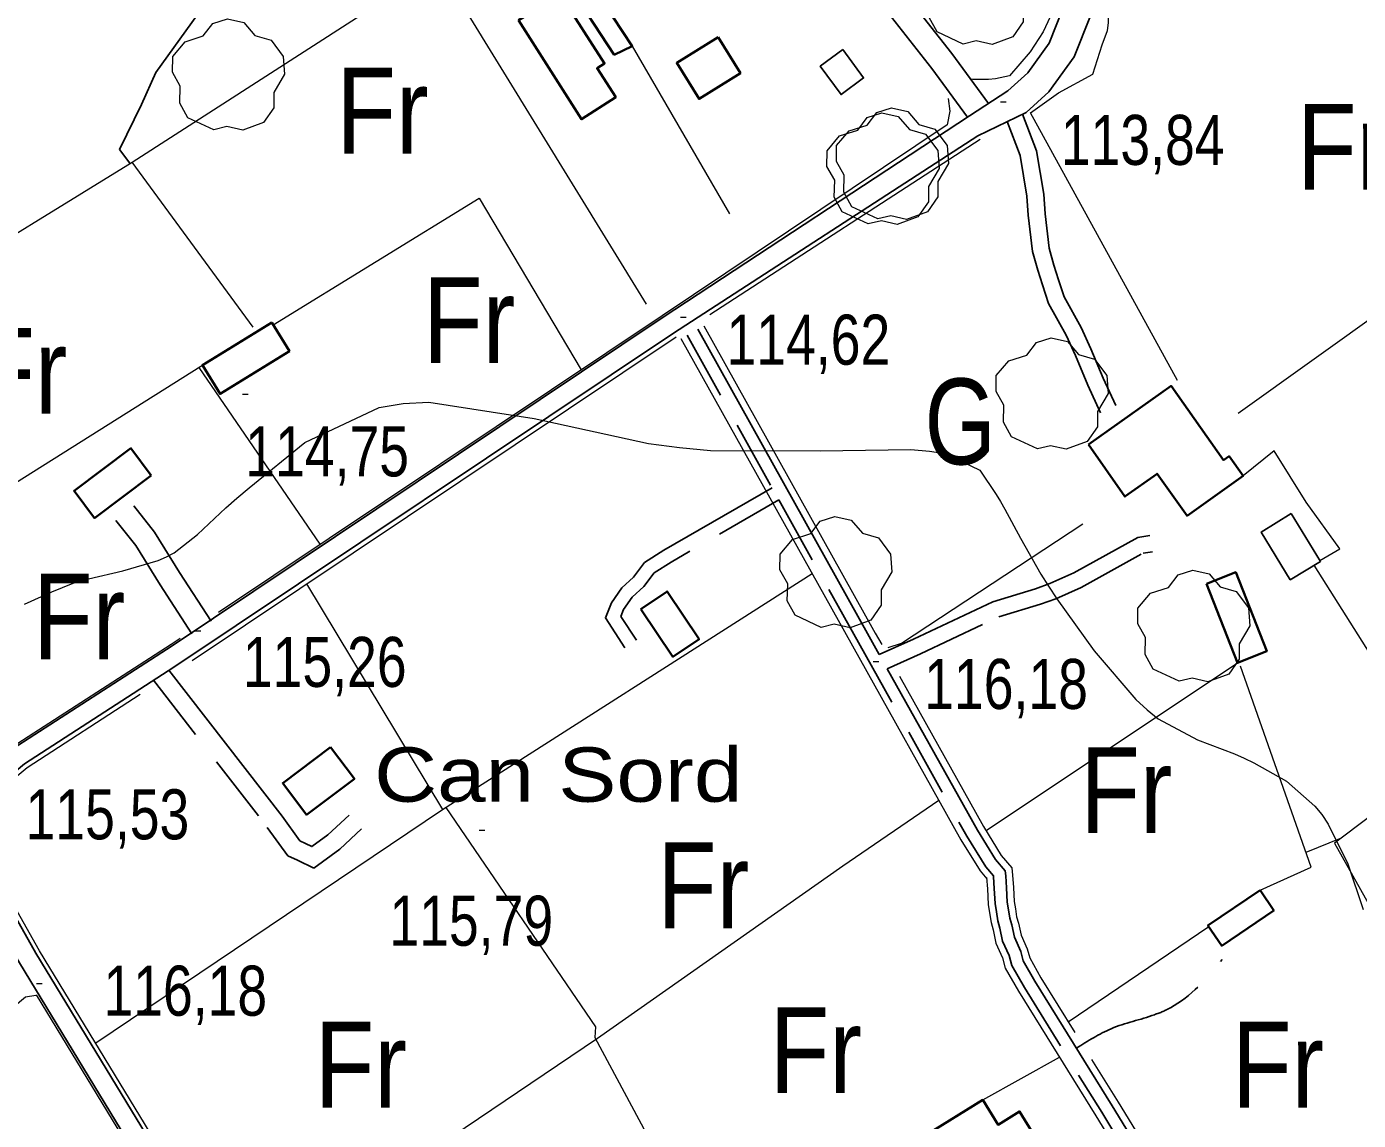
# Model space of a CAD drawing. Extents: x 487425 to 492029, y 4383576 to 4386788.
# Drawn here: x 490307.6 to 490540.5, y 4386113.7 to 4386304.9 of the extents above; entities that cross this region are included whole.
import ezdxf
from ezdxf.enums import TextEntityAlignment as Align

# ---------------------------------------------------------------- set-up
doc = ezdxf.new("R2010")
doc.units = 0
doc.header["$LTSCALE"] = 4
doc.linetypes.add('LONG_DASHED', pattern=[7.5, 6, -1.5])
doc.linetypes.add('MEDIUM_DASHED', pattern=[4.5, 3, -1.5])
for name, color, linetype, lineweight in [('21', 7, 'Continuous', 25), ('25', 7, 'LONG_DASHED', 25), ('27', 7, 'Continuous', 25), ('29', 7, 'Continuous', 13), ('36', 7, 'Continuous', 25), ('38', 7, 'Continuous', 25), ('47', 7, 'Continuous', 35), ('51', 7, 'Continuous', 13), ('7', 7, 'Continuous', 13), ('9', 7, 'Continuous', 13)]:
    doc.layers.add(name, color=color, linetype=linetype, lineweight=lineweight)
doc.layers.add('31', color=7, linetype='Continuous')
doc.layers.add('5', color=7, linetype='Continuous')

msp = doc.modelspace()

# ---------------------------------------------------------------- linework, layer by layer
at = {"layer": '21'}
for points in [[(490450.34, 4386300.88), (490453.98, 4386295.92), (490450.02, 4386293.01), (490446.38, 4386297.97)], [(490528.76, 4386219.75), (490533.84, 4386211.41), (490528.58, 4386208.2), (490523.5, 4386216.54)]]:
    msp.add_lwpolyline(points, close=True, dxfattribs=at)
at = {"layer": '25'}
msp.add_lwpolyline([(490364.68, 4386339.78), (490352.56, 4386324.7), (490339.63, 4386310.05), (490330.21, 4386296.88), (490327.72, 4386291.26), (490323.88, 4386283.4), (490325.69, 4386281)], dxfattribs=at)
at = {"layer": '27'}
msp.add_spline([(490052.1, 4386271.73), (490087.23, 4386212.09), (490129.91, 4386141.85), (490165.28, 4386085.36), (490209.59, 4386010.47), (490241.89, 4385955.04), (490299.5, 4385863.47), (490312.32, 4385839.66), (490347.47, 4385784.14), (490349.11, 4385779.34), (490350.37, 4385775.14), (490349.31, 4385771.69), (490343.97, 4385765.71), (490336.3, 4385759.96), (490324.95, 4385748.9), (490322.69, 4385746.65), (490312.02, 4385740.31), (490313.14, 4385737.99), (490313.21, 4385734.91), (490312.23, 4385732.74), (490304.48, 4385724.89), (490275.85, 4385753.24), (490254.25, 4385777.23), (490245.58, 4385787.08), (490243.42, 4385790.98), (490244.56, 4385796.45), (490251.34, 4385805.13), (490254.13, 4385810.89), (490250.84, 4385814.2), (490247.58, 4385828.53), (490244.46, 4385838.07), (490237.67, 4385848.81), (490235.73, 4385852.04), (490233.87, 4385854.82), (490232.46, 4385862.02), (490232.86, 4385869.07), (490232.12, 4385873.34), (490226.66, 4385877.48), (490220.22, 4385881.03), (490206.75, 4385887.97), (490189.92, 4385901.74), (490176.68, 4385913.33), (490174.88, 4385913.78), (490170.98, 4385912.44), (490147.97, 4385938.76), (490137.87, 4385947.63), (490128.53, 4385959.21), (490117.86, 4385975.66), (490111.29, 4385982.88), (490092.37, 4386001.68), (490080.33, 4386012.74), (490066.14, 4386028.53), (490064.27, 4386031.53), (490064.65, 4386033.26), (490071.94, 4386039.91), (490095.3, 4386052.66), (490102.88, 4386056.08), (490106.93, 4386056.75), (490118.05, 4386063.76), (490108.84, 4386068.44), (490095.91, 4386080.02), (490085.82, 4386092.5), (490079.84, 4386098.82), (490076.03, 4386102.95), (490055.9, 4386114.19), (490035.27, 4386110.65), (490027.31, 4386106.25), (490022.8, 4386103.49), (490016.87, 4386100.88), (490009.59, 4386100.23), (490007.04, 4386100.24), (489993.29, 4386115.35), (489978.27, 4386132.49), (489957.65, 4386157.07), (489944.5, 4386171.88), (489944.5, 4386171.96), (489967.13, 4386193.11), (489991.2, 4386215.98), (490015.33, 4386237.65), (490034.88, 4386255.81), (490049.99, 4386269.79)], degree=3, dxfattribs=at)
at = {"layer": '29'}
for points in [[(490471.38, 4386301.83), (490466.84, 4386303.95), (490465.43, 4386306.49), (490465.53, 4386309.47), (490464.16, 4386311.88), (490464.2, 4386314.63), (490466.36, 4386317.23), (490469.55, 4386318.23), (490471.2, 4386320.42), (490473.77, 4386321.25), (490476.63, 4386320.6), (490478.58, 4386318.33), (490481.39, 4386317.51), (490483.52, 4386314.66), (490483.76, 4386311.53), (490481.88, 4386308.38), (490481.88, 4386305.7), (490480.06, 4386303.09), (490476.44, 4386301.75), (490473.67, 4386302.38)], [(490340.34, 4386286.85), (490335.8, 4386288.97), (490334.39, 4386291.51), (490334.49, 4386294.49), (490333.12, 4386296.9), (490333.16, 4386299.65), (490335.32, 4386302.25), (490338.51, 4386303.25), (490340.16, 4386305.44), (490342.73, 4386306.27), (490345.59, 4386305.62), (490347.54, 4386303.35), (490350.35, 4386302.53), (490352.48, 4386299.68), (490352.72, 4386296.55), (490350.84, 4386293.4), (490350.84, 4386290.72), (490349.02, 4386288.11), (490345.4, 4386286.77), (490342.63, 4386287.4)], [(490456.44, 4386271.28), (490451.9, 4386273.4), (490450.49, 4386275.94), (490450.59, 4386278.92), (490449.22, 4386281.33), (490449.26, 4386284.08), (490451.42, 4386286.68), (490454.61, 4386287.68), (490456.26, 4386289.87), (490458.83, 4386290.7), (490461.69, 4386290.05), (490463.64, 4386287.78), (490466.45, 4386286.96), (490468.58, 4386284.11), (490468.82, 4386280.98), (490466.94, 4386277.83), (490466.94, 4386275.15), (490465.12, 4386272.54), (490461.5, 4386271.2), (490458.73, 4386271.83)], [(490454.79, 4386270.39), (490450.25, 4386272.51), (490448.84, 4386275.05), (490448.94, 4386278.03), (490447.57, 4386280.44), (490447.61, 4386283.19), (490449.77, 4386285.79), (490452.96, 4386286.79), (490454.61, 4386288.98), (490457.18, 4386289.81), (490460.04, 4386289.16), (490461.99, 4386286.89), (490464.8, 4386286.07), (490466.93, 4386283.22), (490467.17, 4386280.09), (490465.29, 4386276.94), (490465.29, 4386274.26), (490463.47, 4386271.65), (490459.85, 4386270.31), (490457.08, 4386270.94)], [(490484.36, 4386231.08), (490479.82, 4386233.2), (490478.41, 4386235.74), (490478.51, 4386238.72), (490477.14, 4386241.13), (490477.18, 4386243.88), (490479.34, 4386246.48), (490482.53, 4386247.48), (490484.18, 4386249.67), (490486.75, 4386250.5), (490489.61, 4386249.85), (490491.56, 4386247.58), (490494.37, 4386246.76), (490496.5, 4386243.91), (490496.74, 4386240.78), (490494.86, 4386237.63), (490494.86, 4386234.95), (490493.04, 4386232.34), (490489.42, 4386231), (490486.65, 4386231.63)], [(490446.55, 4386199.86), (490442.01, 4386201.98), (490440.6, 4386204.52), (490440.7, 4386207.5), (490439.33, 4386209.91), (490439.37, 4386212.66), (490441.53, 4386215.26), (490444.72, 4386216.26), (490446.37, 4386218.45), (490448.94, 4386219.28), (490451.8, 4386218.63), (490453.75, 4386216.36), (490456.56, 4386215.54), (490458.69, 4386212.69), (490458.93, 4386209.56), (490457.05, 4386206.41), (490457.05, 4386203.73), (490455.23, 4386201.12), (490451.61, 4386199.78), (490448.84, 4386200.41)], [(490509.13, 4386190.45), (490504.59, 4386192.57), (490503.18, 4386195.11), (490503.28, 4386198.09), (490501.91, 4386200.5), (490501.95, 4386203.25), (490504.11, 4386205.85), (490507.3, 4386206.85), (490508.95, 4386209.04), (490511.52, 4386209.87), (490514.38, 4386209.22), (490516.33, 4386206.95), (490519.14, 4386206.13), (490521.27, 4386203.28), (490521.51, 4386200.15), (490519.63, 4386197), (490519.63, 4386194.32), (490517.81, 4386191.71), (490514.19, 4386190.37), (490511.42, 4386191)]]:
    msp.add_lwpolyline(points, close=True, dxfattribs=at)
at = {"layer": '36'}
for points in [[(490490.87, 4386315.76), (490488.85, 4386308.16), (490486.42, 4386301.99), (490482.67, 4386296.79), (490479.17, 4386293.66), (490472.49, 4386289.3)], [(490494.31, 4386315.54), (490493.63, 4386306.76), (490490.8, 4386299.6), (490486.38, 4386293.46), (490482.39, 4386289.89), (490473.92, 4386285.81)], [(490472.49, 4386289.3), (490418.92, 4386254.07), (490333.06, 4386196.66), (490305.27, 4386178.7), (490299.18, 4386173.61), (490297.43, 4386168.17), (490296.8, 4386163.38), (490296.79, 4386160.09), (490297.93, 4386156.14), (490306.37, 4386141.26), (490352.95, 4386064.63), (490423, 4385948.82), (490464.34, 4385879.42), (490515.08, 4385794.63), (490515.15, 4385794.51)], [(490473.92, 4386285.81), (490420.74, 4386251.31), (490333.33, 4386192.92)], [(490584.4, 4385683.64), (490562.69, 4385720.59), (490534.26, 4385767.83), (490517.93, 4385796.29), (490467.18, 4385881.11), (490425.84, 4385950.51), (490355.77, 4386066.34), (490309.21, 4386142.93), (490300.99, 4386157.43), (490300.09, 4386160.55), (490300.1, 4386163.15), (490300.67, 4386167.43), (490302.04, 4386171.69), (490307.23, 4386176.04), (490333.33, 4386192.92)]]:
    msp.add_lwpolyline(points, dxfattribs=at)
at = {"layer": '38', "linetype": 'MEDIUM_DASHED'}
msp.add_line((490423.09, 4386250.95), (490437.97, 4386224.29), dxfattribs=at)
at = {"layer": '38'}
for points in [[(490475.82, 4386291.47), (490469.41, 4386300.21), (490462.29, 4386309.25)], [(490472.16, 4386289.08), (490465.93, 4386297.57), (490458.86, 4386306.56)], [(490479.06, 4386288.28), (490481.32, 4386282.36), (490482.54, 4386275.24), (490482.75, 4386271.9), (490483.5, 4386265.56), (490484.42, 4386262.31), (490485.23, 4386259.73), (490486.31, 4386256.48), (490489.4, 4386250.95), (490491.01, 4386247.4), (490493.17, 4386242.21), (490495.41, 4386237.39)], [(490481.74, 4386289.58), (490484.19, 4386283.15), (490485.48, 4386275.59), (490485.7, 4386272.17), (490486.41, 4386266.14), (490487.25, 4386263.16), (490488.05, 4386260.65), (490489.03, 4386257.68), (490492.04, 4386252.29), (490493.73, 4386248.58), (490495.88, 4386243.41), (490498.1, 4386238.64)], [(490424.97, 4386251.99), (490454.95, 4386198.29), (490456.71, 4386195.15)], [(490437.97, 4386224.29), (490419.05, 4386213.35), (490415.68, 4386211.21), (490413.73, 4386208.65), (490411.68, 4386206.76), (490409.86, 4386204.14), (490408.81, 4386201.53), (490412.23, 4386196.32)], [(490339.87, 4386200.94), (490334.35, 4386209.49), (490329.99, 4386216.53), (490326.37, 4386221.09)], [(490456.71, 4386195.15), (490462.72, 4386197.83), (490476.57, 4386204.36), (490484.01, 4386206.62), (490486.52, 4386207.54), (490490.75, 4386209.42), (490501.92, 4386215.58), (490504.05, 4386215.92)], [(490458.1, 4386192.65), (490473.89, 4386164.44), (490477.06, 4386159.29), (490478.72, 4386157.31), (490478.82, 4386156.45), (490478.96, 4386154.34), (490479.1, 4386151.81), (490479.32, 4386150.49), (490479.53, 4386149.03), (490479.9, 4386147.85), (490480.34, 4386145.7), (490481.44, 4386143.24), (490481.88, 4386141.61), (490483.93, 4386138.01), (490497.43, 4386116.24), (490530.41, 4386062.29), (490555.36, 4386020.73)], [(490332.51, 4386192.39), (490352.28, 4386166.85), (490355.4, 4386162.53), (490356.36, 4386162.09), (490357.51, 4386161.54), (490360.3, 4386163.58), (490363.99, 4386167.02)]]:
    msp.add_lwpolyline(points, dxfattribs=at)
at = {"layer": '38', "linetype": 'MEDIUM_DASHED'}
for points in [[(490439.14, 4386222.18), (490420.3, 4386211.29), (490417.34, 4386209.4), (490415.52, 4386207.02), (490413.51, 4386205.16), (490412, 4386202.99), (490411.52, 4386201.8), (490414.25, 4386197.65)], [(490439.14, 4386222.18), (490453.07, 4386197.25), (490472.04, 4386163.35), (490475.32, 4386158.03), (490476.66, 4386156.42), (490476.68, 4386156.26), (490476.82, 4386154.21), (490476.96, 4386151.58), (490477.19, 4386150.16), (490477.43, 4386148.55), (490477.81, 4386147.31), (490478.28, 4386145.04), (490479.41, 4386142.51), (490479.88, 4386140.79), (490482.08, 4386136.91), (490495.6, 4386115.11), (490500.63, 4386106.89)], [(490336.49, 4386198.75), (490330.94, 4386207.33), (490326.69, 4386214.2), (490323.21, 4386218.58)], [(490458.1, 4386192.65), (490463.91, 4386195.24), (490477.6, 4386201.69), (490484.92, 4386203.91), (490487.59, 4386204.89), (490492.02, 4386206.86), (490502.87, 4386212.84), (490504.5, 4386213.1)], [(490329.78, 4386190.63), (490349.68, 4386164.91), (490353.27, 4386159.93), (490354.99, 4386159.15), (490357.85, 4386157.77), (490362.37, 4386161.08), (490366.2, 4386164.65)]]:
    msp.add_lwpolyline(points, dxfattribs=at)
at = {"layer": '38', "linetype": 'LONG_DASHED'}
msp.add_spline([(490491.19, 4386126.29), (490497.28, 4386129.72), (490504.86, 4386132.17), (490507.63, 4386133.37), (490516.66, 4386141.81)], degree=3, dxfattribs=at)
at = {"layer": '47'}
for points in [[(490410.38, 4386299.94), (490402.24, 4386312.34), (490404.43, 4386313.77), (490401.36, 4386318.45), (490404.63, 4386320.59), (490409.29, 4386313.46), (490406.75, 4386311.8), (490413.49, 4386301.47)], [(490393.6, 4386305.99), (490404.64, 4386288.71), (490410.63, 4386292.55), (490407.37, 4386297.61), (490408.68, 4386298.45), (490401.02, 4386310.38)], [(490428.53, 4386303.04), (490432.44, 4386296.74), (490425.2, 4386292.25), (490421.29, 4386298.55)], [(490350.48, 4386253.18), (490338.36, 4386245.71), (490341.45, 4386240.69), (490353.57, 4386248.16)], [(490493.31, 4386231.86), (490507.74, 4386242.09), (490516.93, 4386229.11), (490517.87, 4386229.78), (490520.32, 4386226.34), (490510.54, 4386219.39), (490505.3, 4386226.74), (490499.67, 4386222.73)], [(490329.41, 4386226.4), (490319.48, 4386218.97), (490315.91, 4386223.74), (490325.84, 4386231.17)], [(490513.93, 4386207.5), (490519.35, 4386193.69), (490524.47, 4386195.7), (490519.05, 4386209.51)], [(490415.02, 4386203.08), (490420.62, 4386194.73), (490425.2, 4386197.8), (490419.6, 4386206.15)], [(490360.74, 4386178.95), (490352.4, 4386172.64), (490356.58, 4386167.11), (490364.92, 4386173.42)], [(490523.29, 4386153.94), (490514.18, 4386147.75), (490516.59, 4386144.21), (490525.7, 4386150.4)], [(490464.83, 4386111.08), (490474.82, 4386117.27), (490477.49, 4386112.94), (490481.25, 4386115.25), (490486.02, 4386107.48), (490475.62, 4386101.09), (490473.67, 4386104.24), (490470.57, 4386102.32)]]:
    msp.add_lwpolyline(points, close=True, dxfattribs=at)
at = {"layer": '51'}
for p, q in [((490413.49, 4386301.47), (490430.52, 4386272.16)), ((490474.35, 4386285.15), (490427.11, 4386254.51)), ((490326.01, 4386281.19), (490347.18, 4386252.37)), ((490519.49, 4386237.33), (490571.01, 4386274.2)), ((490273.46, 4386204.87), (490339.65, 4386246.51)), ((490358.96, 4386214.4), (490337.77, 4386245.32)), ((490356.56, 4386207.46), (490380.35, 4386168.02)), ((490475.38, 4386164.36), (490519.35, 4386193.69)), ((490531.33, 4386160.56), (490537.51, 4386163.07)), ((490489.77, 4386130.9), (490514.31, 4386147.58)), ((490474.82, 4386117.27), (490488.21, 4386124.73))]:
    msp.add_line(p, q, dxfattribs=at)
for points in [[(490305.27, 4386436.43), (490345.95, 4386370.24), (490415.95, 4386256.36)], [(490508.88, 4386243.05), (490483.15, 4386289.83), (490488.03, 4386293.34), (490494.04, 4386296.55), (490495.71, 4386301.72), (490496.61, 4386304.19), (490496.77, 4386305.54), (490496.85, 4386307.57), (490539.58, 4386332.41)], [(490489.47, 4386323.18), (490489.38, 4386316.88), (490488.16, 4386310.06), (490485.37, 4386304), (490483.11, 4386300.48), (490479.5, 4386296.29), (490477.02, 4386295.78), (490475.82, 4386295.63), (490473.05, 4386295.64), (490472.67, 4386295.71)], [(490254.11, 4386236.9), (490326.05, 4386281.22), (490379.53, 4386315.63)], [(490468.76, 4386292.35), (490469.06, 4386290.1), (490468.6, 4386287.7)], [(490468.6, 4386287.7), (490418.74, 4386254.35), (490341.17, 4386202.5)], [(490350.75, 4386252.75), (490386.76, 4386274.89), (490404.58, 4386244.89)], [(490426.03, 4386252.58), (490456.01, 4386198.88), (490457.14, 4386196.87)], [(490336.54, 4386194.08), (490421.17, 4386250.65), (490421.18, 4386250.66)], [(490422.03, 4386250.36), (490452.01, 4386196.66), (490471, 4386162.74), (490474.33, 4386157.32), (490475.5, 4386155.92), (490475.47, 4386156.14), (490475.61, 4386154.14), (490475.75, 4386151.45), (490475.99, 4386149.97), (490476.25, 4386148.28), (490476.64, 4386147.01), (490477.12, 4386144.67), (490478.27, 4386142.1), (490478.75, 4386140.32), (490481.04, 4386136.29), (490494.57, 4386114.47), (490499.52, 4386106.38)], [(490531.37, 4386221.77), (490525.77, 4386230.71), (490520.32, 4386226.34)], [(490533.76, 4386211.55), (490537.27, 4386213.58), (490531.37, 4386221.77)], [(490458.26, 4386196.35), (490460.59, 4386197.09), (490492.29, 4386217.99)], [(490319.69, 4386127.22), (490380.35, 4386168.02), (490444.95, 4386209.31)], [(490532.71, 4386210.72), (490554.7, 4386175.96), (490536.29, 4386162.15), (490564.93, 4386111.15), (490565.63, 4386111.22)], [(490302.91, 4386177.18), (490305.06, 4386178.98), (490332.87, 4386196.95), (490334.44, 4386198)], [(490523.29, 4386153.94), (490532.23, 4386157.96), (490519.89, 4386193.09)], [(490460.23, 4386191.34), (490474.94, 4386165.06), (490478.05, 4386160), (490479.89, 4386157.81), (490480.03, 4386156.56), (490480.17, 4386154.41), (490480.31, 4386151.94), (490480.52, 4386150.68), (490480.72, 4386149.3), (490481.08, 4386148.15), (490481.5, 4386146.07), (490482.59, 4386143.65), (490483.01, 4386142.08), (490484.97, 4386138.63), (490490.92, 4386129.05)], [(490457.99, 4385898.11), (490426.52, 4385950.92), (490356.45, 4386066.75), (490309.89, 4386143.33), (490301.72, 4386157.74), (490300.88, 4386160.66), (490300.89, 4386163.1), (490301.44, 4386167.26), (490302.72, 4386171.23), (490307.7, 4386175.4), (490327.46, 4386188.18)], [(490344.85, 4386085.84), (490407.44, 4386128.04), (490450.35, 4386158.21), (490467.15, 4386169.64)], [(490380.9, 4386168.37), (490407.08, 4386130.07), (490406.99, 4386128.2), (490430.03, 4386085.16), (490453.75, 4386044), (490481.23, 4386005.08)], [(490309.52, 4386135.39), (490309.24, 4386135.54), (490307.44, 4386135.25), (490294.44, 4386124.41), (490293.46, 4386123.22), (490292.26, 4386122.32)], [(490402.73, 4385981.64), (490352.64, 4386064.44), (490309.37, 4386135.62)], [(490493.84, 4386124.35), (490498.46, 4386116.88), (490531.45, 4386062.92), (490555.45, 4386022.97)]]:
    msp.add_lwpolyline(points, dxfattribs=at)
at = {"layer": '7'}
for p, q in [((490477.92, 4386291.74), (490478.92, 4386291.74)), ((490421.95, 4386254.12), (490422.95, 4386254.12)), ((490345.35, 4386240.63), (490346.35, 4386240.63)), ((490337.05, 4386199.26), (490338.05, 4386199.26)), ((490455.66, 4386193.88), (490456.66, 4386193.88)), ((490386.73, 4386164.4), (490387.73, 4386164.4)), ((490309.35, 4386137.64), (490310.35, 4386137.64))]:
    msp.add_line(p, q, dxfattribs=at)
at = {"layer": '9'}
msp.add_lwpolyline([(490307.25, 4386203.94), (490312.01, 4386206.08), (490315.73, 4386207.59), (490317.02, 4386207.99), (490318.43, 4386208.38), (490324.46, 4386209.77), (490330.59, 4386211.56), (490332.05, 4386212.21), (490333.41, 4386212.93), (490337.49, 4386216.11), (490342.44, 4386220.78), (490344.36, 4386222.45), (490346.51, 4386224.27), (490356.24, 4386232.21), (490369.25, 4386238.31), (490373.47, 4386238.99), (490377.95, 4386239.22), (490396.39, 4386236.38), (490416.34, 4386232.03), (490421.77, 4386231.31), (490427.18, 4386230.81), (490446.38, 4386230.72), (490462.21, 4386230.98), (490465.47, 4386230.7), (490468.26, 4386230.25), (490474.29, 4386227.34), (490477.14, 4386223.12), (490477.91, 4386221.86), (490478.67, 4386220.55), (490481.38, 4386215.45), (490484.97, 4386209.16), (490486.3, 4386207.09), (490487.77, 4386204.89), (490494.28, 4386195.77), (490501.59, 4386187.28), (490503.56, 4386185.47), (490505.5, 4386183.9), (490512.35, 4386180.2), (490518.81, 4386177.77), (490520.52, 4386177.01), (490522.19, 4386176.21), (490527.9, 4386172.98), (490532.88, 4386168.64), (490534.09, 4386167.14), (490535.21, 4386165.5), (490538.64, 4386158.52), (490541.31, 4386150.53)], dxfattribs=at)

# ---------------------------------------------------------------- texts
at = {"layer": '31'}
for s, width, p in [('Fr', 0.85, (490369.84, 4386282.7)), ('Fr', 0.85, (490537.8, 4386276.38)), ('Fr', 0.85, (490384.99, 4386246.06)), ('Fr', 0.85, (490306.69, 4386237.22)), ('G', 0.8, (490470.87, 4386228.37)), ('Fr', 0.85, (490316.8, 4386194.26)), ('Fr', 0.85, (490499.92, 4386163.93)), ('Fr', 0.85, (490425.92, 4386147.27)), ('Fr', 0.85, (490445.61, 4386118.45)), ('Fr', 0.85, (490366.05, 4386115.92)), ('Fr', 0.85, (490526.44, 4386115.92))]:
    msp.add_text(s, height=15, dxfattribs=dict(at, width=width)).set_placement(p, align=Align.CENTER)
at = {"layer": '5', "width": 1.2}
msp.add_text('Can Sord', height=9.5, dxfattribs=at).set_placement((490432.78, 4386169.39), align=Align.RIGHT)
at = {"layer": '7', "width": 0.8}
for s, p in [('113,84', (490488.46, 4386280.71)), ('114,62', (490430, 4386245.79)), ('114,75', (490345.85, 4386226.26)), ('115,26', (490345.43, 4386189.46)), ('116,18', (490464.57, 4386185.61)), ('115,53', (490307.43, 4386162.82)), ('115,79', (490371.05, 4386144.22)), ('116,18', (490321.05, 4386131.99))]:
    msp.add_text(s, height=8.75, dxfattribs=at).set_placement(p)

doc.saveas('drawing.dxf')
